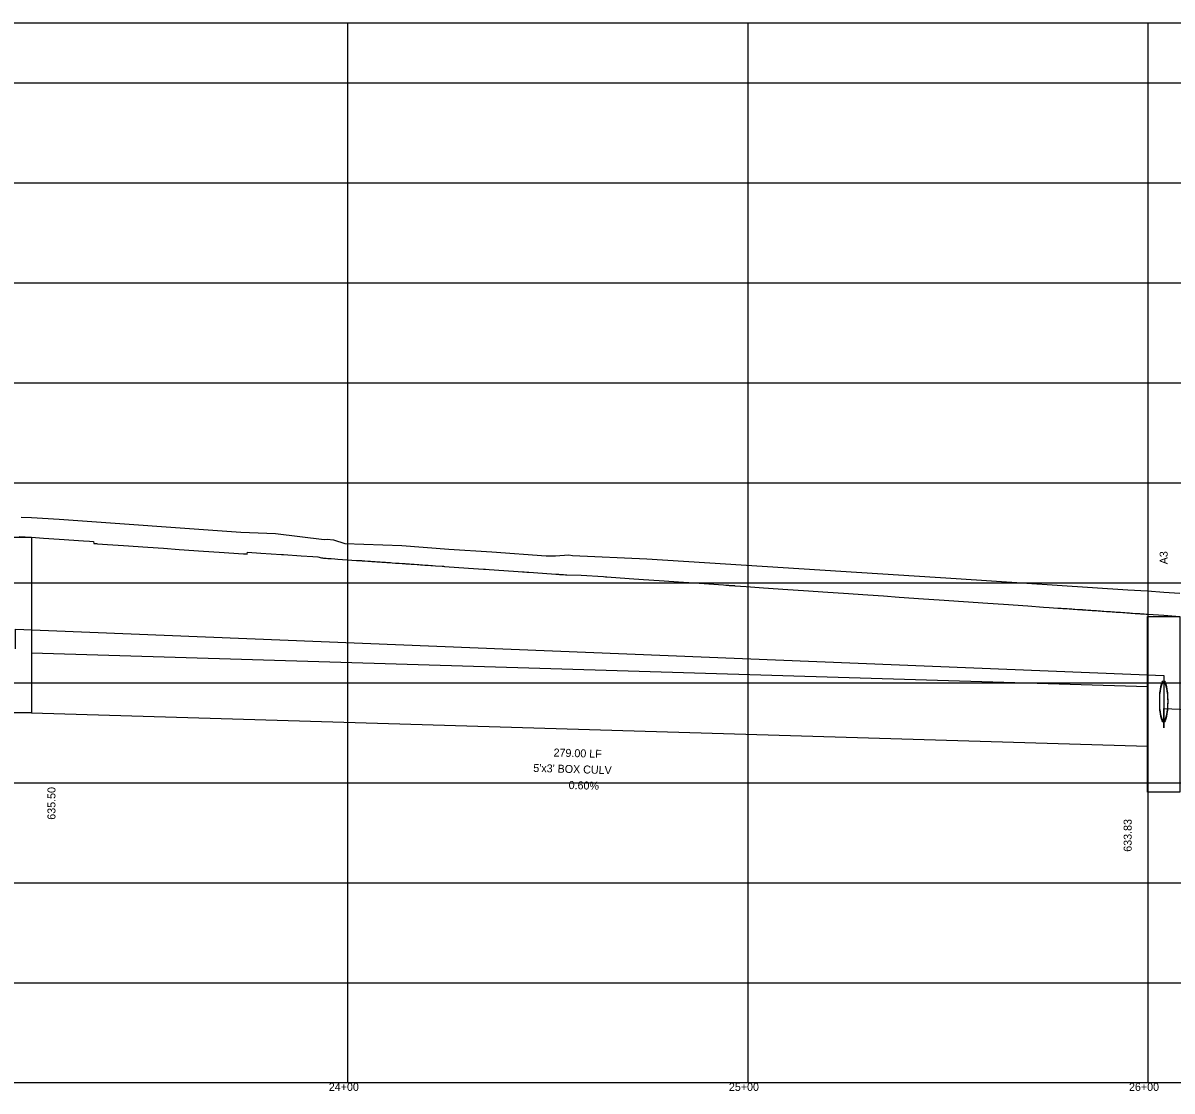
# Model space of a CAD drawing. Extents: x 2252703 to 2264864, y 13787568 to 13790989.
# Drawn here: x 2260230.8 to 2260518, y 13790698.5 to 13790965.5 of the extents above; entities that cross this region are included whole.
import ezdxf

# ---------------------------------------------------------------- set-up
doc = ezdxf.new("R2010")
doc.units = 0
for name, color, linetype in [('blank4', 7, 'Continuous'), ('D_DRN_PROF_HGL', 7, 'Continuous'), ('D_PROF_1', 7, 'Continuous'), ('D_PROF_NOTES_1', 7, 'Continuous'), ('Default', 7, 'Continuous'), ('Drain_PipeInside', 7, 'Continuous'), ('E_Terrain', 7, 'Continuous'), ('Inlet', 7, 'Continuous'), ('z - Construction', 7, 'Continuous')]:
    doc.layers.add(name, color=color, linetype=linetype)

msp = doc.modelspace()

# ---------------------------------------------------------------- linework, layer by layer
at = {"layer": 'blank4'}
msp.add_lwpolyline([(2257912.03, 13790700.51), (2257912.03, 13790965.51), (2261066.03, 13790965.51), (2261066.03, 13790700.51)], close=True, dxfattribs=at)
at = {"layer": 'D_DRN_PROF_HGL'}
msp.add_line((2260515.91, 13790802.39), (2260515.91, 13790789.3), dxfattribs=at)
for points in [[(2260228.91, 13790809.05), (2260228.91, 13790813.97), (2260515.91, 13790802.39)], [(2260515.91, 13790789.3), (2260515.91, 13790794.15), (2260770.91, 13790783.51)]]:
    msp.add_lwpolyline(points, dxfattribs=at)
at = {"layer": 'D_PROF_1'}
msp.add_lwpolyline([(2260229.82, 13790837.16), (2260232.91, 13790836.95), (2260232.91, 13790836.95), (2260235.91, 13790836.74), (2260239.82, 13790836.47), (2260245.91, 13790836.05), (2260247.44, 13790835.94), (2260248.43, 13790835.88), (2260248.53, 13790835.38), (2260248.68, 13790835.37), (2260249.14, 13790835.34), (2260249.43, 13790835.32), (2260251.96, 13790835.14), (2260255.91, 13790834.87), (2260261.99, 13790834.45), (2260265.91, 13790834.18), (2260269.82, 13790833.91), (2260275.91, 13790833.49), (2260279.82, 13790833.22), (2260285.91, 13790832.8), (2260286.38, 13790832.77), (2260286.68, 13790832.75), (2260286.83, 13790832.74), (2260286.93, 13790833.22), (2260290.24, 13790832.99), (2260295.38, 13790832.64), (2260295.58, 13790832.62), (2260295.91, 13790832.6), (2260300.36, 13790832.29), (2260303.22, 13790832.1), (2260304.53, 13790832.01), (2260305.37, 13790831.77), (2260305.7, 13790831.75), (2260305.91, 13790831.73), (2260305.93, 13790831.73), (2260305.97, 13790831.73), (2260306.22, 13790831.71), (2260306.38, 13790831.7), (2260306.59, 13790831.69), (2260307.02, 13790831.66), (2260307.1, 13790831.65), (2260307.34, 13790831.64), (2260307.71, 13790831.61), (2260307.75, 13790831.61), (2260307.8, 13790831.6), (2260308.76, 13790831.54), (2260309.53, 13790831.48), (2260314.19, 13790831.16), (2260314.55, 13790831.14), (2260315.38, 13790831.08), (2260315.58, 13790831.07), (2260315.91, 13790831.04), (2260315.95, 13790831.04), (2260316.03, 13790831.04), (2260316.28, 13790831.02), (2260316.97, 13790830.97), (2260317.15, 13790830.96), (2260317.16, 13790830.96), (2260317.67, 13790830.92), (2260317.98, 13790830.9), (2260318.04, 13790830.9), (2260318.55, 13790830.86), (2260318.82, 13790830.84), (2260319.24, 13790830.81), (2260320.02, 13790830.76), (2260320.11, 13790830.75), (2260320.48, 13790830.73), (2260321.25, 13790830.68), (2260321.38, 13790830.67), (2260321.72, 13790830.64), (2260322.24, 13790830.61), (2260322.29, 13790830.6), (2260322.31, 13790830.6), (2260322.63, 13790830.58), (2260323.11, 13790830.55), (2260323.87, 13790830.49), (2260324.36, 13790830.46), (2260324.84, 13790830.43), (2260325.59, 13790830.38), (2260325.71, 13790830.37), (2260325.91, 13790830.35), (2260326.25, 13790830.33), (2260326.47, 13790830.32), (2260326.76, 13790830.3), (2260327.28, 13790830.26), (2260327.32, 13790830.26), (2260327.35, 13790830.25), (2260327.38, 13790830.25), (2260327.85, 13790830.22), (2260328.58, 13790830.17), (2260329.3, 13790830.12), (2260329.76, 13790830.09), (2260330.12, 13790830.06), (2260330.68, 13790830.02), (2260331.25, 13790829.99), (2260331.61, 13790829.96), (2260332.07, 13790829.93), (2260332.77, 13790829.88), (2260332.92, 13790829.87), (2260333.14, 13790829.85), (2260333.87, 13790829.8), (2260335.55, 13790829.69), (2260335.91, 13790829.67), (2260336.17, 13790829.66), (2260336.17, 13790829.65), (2260336.17, 13790829.65), (2260337.32, 13790829.57), (2260343.41, 13790829.15), (2260345.91, 13790828.97), (2260346.43, 13790828.94), (2260347.29, 13790828.88), (2260353.38, 13790828.46), (2260354.54, 13790828.38), (2260355.61, 13790828.3), (2260355.91, 13790828.28), (2260356.04, 13790828.28), (2260356.76, 13790828.23), (2260357.25, 13790828.19), (2260362.92, 13790827.8), (2260363.96, 13790827.73), (2260364.68, 13790827.68), (2260364.9, 13790827.66), (2260365.22, 13790827.64), (2260365.29, 13790827.64), (2260365.67, 13790827.61), (2260365.84, 13790827.6), (2260365.87, 13790827.6), (2260365.91, 13790827.59), (2260366.4, 13790827.56), (2260366.71, 13790827.54), (2260370.31, 13790827.47), (2260375.91, 13790827.08), (2260376.41, 13790827.05), (2260376.74, 13790827.02), (2260376.74, 13790827.02), (2260376.75, 13790827.02), (2260382.33, 13790826.64), (2260385.91, 13790826.39), (2260389.82, 13790826.12), (2260395.91, 13790825.7), (2260399.82, 13790825.43), (2260405.91, 13790825.01), (2260406.48, 13790824.97), (2260406.86, 13790824.95), (2260406.98, 13790824.94), (2260407.17, 13790824.92), (2260407.3, 13790824.91), (2260407.39, 13790824.91), (2260407.61, 13790824.89), (2260407.95, 13790824.87), (2260408.29, 13790824.85), (2260408.51, 13790824.83), (2260408.6, 13790824.83), (2260408.74, 13790824.82), (2260411.54, 13790824.62), (2260415.91, 13790824.32), (2260421.99, 13790823.9), (2260425.91, 13790823.63), (2260431.99, 13790823.21), (2260435.91, 13790822.94), (2260441.99, 13790822.52), (2260445.91, 13790822.25), (2260449.82, 13790821.98), (2260455.91, 13790821.56), (2260459.82, 13790821.29), (2260465.91, 13790820.87), (2260471.99, 13790820.45), (2260475.91, 13790820.18), (2260481.99, 13790819.76), (2260485.91, 13790819.49), (2260487.31, 13790819.39), (2260489.49, 13790819.24), (2260489.96, 13790819.21), (2260490.26, 13790819.19), (2260490.7, 13790819.16), (2260491.38, 13790819.11), (2260491.75, 13790819.09), (2260492.32, 13790819.05), (2260492.43, 13790819.04), (2260492.51, 13790819.04), (2260492.97, 13790819), (2260493.27, 13790818.98), (2260493.7, 13790818.95), (2260494.38, 13790818.91), (2260495.04, 13790818.86), (2260495.46, 13790818.83), (2260495.54, 13790818.83), (2260495.59, 13790818.82), (2260495.71, 13790818.81), (2260495.91, 13790818.8), (2260495.91, 13790818.8), (2260495.92, 13790818.8), (2260496.12, 13790818.79), (2260496.44, 13790818.76), (2260496.97, 13790818.73), (2260497.31, 13790818.7), (2260497.35, 13790818.7), (2260497.43, 13790818.7), (2260497.59, 13790818.68), (2260497.7, 13790818.68), (2260498.01, 13790818.66), (2260498.5, 13790818.62), (2260499.13, 13790818.58), (2260499.54, 13790818.55), (2260500.16, 13790818.51), (2260500.56, 13790818.48), (2260500.96, 13790818.45), (2260501.59, 13790818.41), (2260502.21, 13790818.37), (2260502.62, 13790818.34), (2260503.01, 13790818.31), (2260503.63, 13790818.27), (2260504.04, 13790818.24), (2260504.67, 13790818.2), (2260505.09, 13790818.17), (2260505.74, 13790818.12), (2260505.84, 13790818.12), (2260505.91, 13790818.11), (2260506.23, 13790818.09), (2260506.73, 13790818.05), (2260507.33, 13790818.01), (2260507.71, 13790817.99), (2260508.13, 13790817.96), (2260508.79, 13790817.91), (2260508.88, 13790817.91), (2260508.93, 13790817.9), (2260508.99, 13790817.9), (2260509.09, 13790817.89), (2260509.5, 13790817.86), (2260509.77, 13790817.84), (2260509.9, 13790817.84), (2260510.1, 13790817.82), (2260510.15, 13790817.82), (2260510.22, 13790817.81), (2260511.04, 13790817.76), (2260511.57, 13790817.72), (2260511.91, 13790817.7), (2260511.91, 13790817.7), (2260513.26, 13790817.6), (2260515.91, 13790817.42), (2260515.91, 13790817.42), (2260519.91, 13790817.14)], dxfattribs=at)
at = {"layer": 'Default'}
for p, q in [((2260312.03, 13790700.51), (2260312.03, 13790965.51)), ((2260412.03, 13790700.51), (2260412.03, 13790965.51)), ((2260512.03, 13790700.51), (2260512.03, 13790965.51))]:
    msp.add_line(p, q, dxfattribs=at)
at = {"layer": 'Drain_PipeInside'}
for p, q in [((2260232.91, 13790808.03), (2260511.91, 13790799.66)), ((2260232.91, 13790793.03), (2260511.91, 13790784.66))]:
    msp.add_line(p, q, dxfattribs=at)
for centre in [(2260515.91, 13790796.07), (2260515.91, 13790795.67)]:
    msp.add_ellipse(centre, major_axis=(0, 5), ratio=0.2, dxfattribs=at)
at = {"layer": 'E_Terrain'}
msp.add_lwpolyline([(2260230.33, 13790841.97), (2260232.91, 13790841.84), (2260232.91, 13790841.84), (2260239.87, 13790841.48), (2260285.28, 13790838.2), (2260293.95, 13790837.89), (2260306.06, 13790836.37), (2260306.8, 13790836.46), (2260308.43, 13790836.29), (2260311.24, 13790835.4), (2260325.53, 13790834.87), (2260337.21, 13790833.92), (2260347.99, 13790833.31), (2260361.59, 13790832.25), (2260363.94, 13790832.32), (2260367.19, 13790832.55), (2260368.14, 13790832.36), (2260386.74, 13790831.52), (2260406.4, 13790830.32), (2260464.08, 13790826.66), (2260506.95, 13790823.81), (2260511.91, 13790823.5), (2260511.91, 13790823.5), (2260515.91, 13790823.24), (2260515.91, 13790823.24), (2260519.91, 13790822.99)], dxfattribs=at)
at = {"layer": 'Inlet'}
for points in [[(2260224.91, 13790836.96), (2260232.91, 13790836.96), (2260232.91, 13790793.03), (2260224.91, 13790793.03)], [(2260511.91, 13790817.16), (2260519.91, 13790817.16), (2260519.91, 13790773.17), (2260511.91, 13790773.17)]]:
    msp.add_lwpolyline(points, close=True, dxfattribs=at)
at = {"layer": 'z - Construction'}
for p, q in [((2257912.03, 13790950.51), (2261066.03, 13790950.51)), ((2257912.03, 13790925.51), (2261066.03, 13790925.51)), ((2257912.03, 13790900.51), (2261066.03, 13790900.51)), ((2257912.03, 13790875.51), (2261066.03, 13790875.51)), ((2257912.03, 13790850.51), (2261066.03, 13790850.51)), ((2257912.03, 13790825.51), (2261066.03, 13790825.51)), ((2257912.03, 13790800.51), (2261066.03, 13790800.51)), ((2257912.03, 13790775.51), (2261066.03, 13790775.51)), ((2257912.03, 13790750.51), (2261066.03, 13790750.51)), ((2257912.03, 13790725.51), (2261066.03, 13790725.51))]:
    msp.add_line(p, q, dxfattribs=at)

# ---------------------------------------------------------------- texts
at = {"layer": 'D_PROF_NOTES_1'}
for s, rotation, p in [('A3', 90, (2260516.91, 13790830.17)), ('279.00 LF', 358.2816, (2260363.39, 13790782.12)), ("5'x3' BOX CULV", 358.2816, (2260358.33, 13790778.27)), ('635.50', 90, (2260238.91, 13790766.31)), ('0.60%', 358.2816, (2260367.16, 13790774)), ('633.83', 90, (2260507.91, 13790758.3))]:
    msp.add_text(s, height=2, rotation=rotation, dxfattribs=at).set_placement(p)
at = {"layer": 'Default'}
for s, p in [('24+00', (2260307.24, 13790698.51)), ('25+00', (2260407.24, 13790698.51)), ('26+00', (2260507.24, 13790698.51))]:
    msp.add_text(s, height=2, dxfattribs=at).set_placement(p)

doc.saveas('drawing.dxf')
